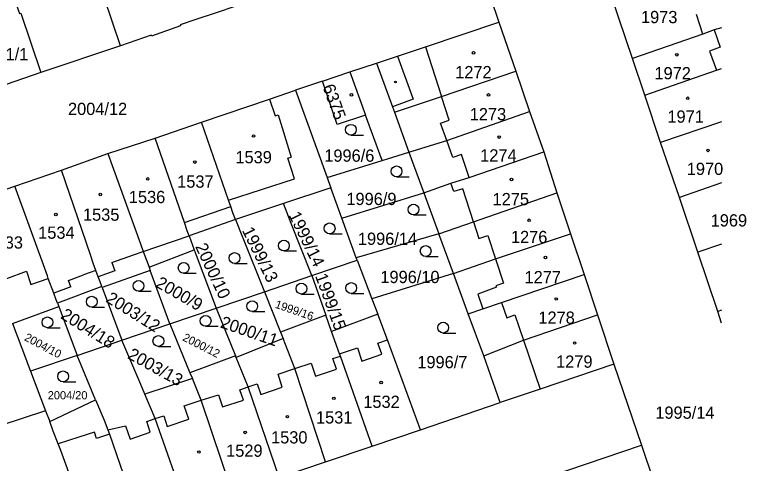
# Model space of a CAD drawing. Extents: x -564952 to -564307, y -1202373 to -1201847.
# Drawn here: x -564412.8 to -564311.2, y -1202149.3 to -1202086.9 of the extents above; entities that cross this region are included whole.
import ezdxf

# ---------------------------------------------------------------- set-up
doc = ezdxf.new("R2010")
doc.units = 0
for name, color, linetype in [('Hranice parcel', 7, 'Continuous'), ('Parcelní čísla', 7, 'Continuous'), ('Vnitřní kresba', 7, 'Continuous'), ('Značky budov', 7, 'Continuous'), ('Značky kultur', 7, 'Continuous')]:
    doc.layers.add(name, color=color, linetype=linetype)

msp = doc.modelspace()

# ---------------------------------------------------------------- linework, layer by layer
at = {"layer": 'Hranice parcel'}
for p, q in [((-564350.67, -1202072.89), (-564345.58, -1202087.99)), ((-564398.11, -1202091.24), (-564401.53, -1202081.18)), ((-564327.05, -1202093.01), (-564330.1, -1202083.96)), ((-564355.78, -1202091.38), (-564345.58, -1202087.99)), ((-564345.58, -1202087.99), (-564343.21, -1202094.78)), ((-564398.11, -1202091.24), (-564409.17, -1202094.97)), ((-564325.33, -1202098.13), (-564327.05, -1202093.01)), ((-564366.26, -1202094.88), (-564362.59, -1202093.65)), ((-564409.17, -1202094.97), (-564416.99, -1202097.64)), ((-564370.08, -1202096.16), (-564366.26, -1202094.88)), ((-564366.26, -1202094.88), (-564364.09, -1202100.88)), ((-564343.21, -1202094.78), (-564341.34, -1202100.38)), ((-564370.08, -1202096.16), (-564373.83, -1202097.42)), ((-564368.05, -1202102.21), (-564370.08, -1202096.16)), ((-564373.83, -1202097.42), (-564369.45, -1202109.57)), ((-564323.12, -1202104.71), (-564325.33, -1202098.13)), ((-564341.34, -1202100.38), (-564339.35, -1202105.98)), ((-564364.09, -1202100.88), (-564368.05, -1202102.21)), ((-564361.81, -1202107.21), (-564364.09, -1202100.88)), ((-564393.32, -1202104.11), (-564386.86, -1202101.86)), ((-564314.65, -1202101.83), (-564323.12, -1202104.71)), ((-564399.87, -1202106.23), (-564393.32, -1202104.11)), ((-564320.52, -1202112.35), (-564323.12, -1202104.71)), ((-564406.3, -1202108.52), (-564399.87, -1202106.23)), ((-564399.87, -1202106.23), (-564395.37, -1202118.77)), ((-564361.81, -1202107.21), (-564358.07, -1202106.05)), ((-564358.07, -1202106.05), (-564356.01, -1202111.68)), ((-564339.35, -1202105.98), (-564337.55, -1202111.69)), ((-564369.45, -1202109.57), (-564361.81, -1202107.21)), ((-564412.8, -1202110.76), (-564406.3, -1202108.52)), ((-564369.45, -1202109.57), (-564369.31, -1202109.97)), ((-564369.31, -1202109.97), (-564368.94, -1202110.98)), ((-564314.65, -1202110.31), (-564320.52, -1202112.35)), ((-564419.59, -1202113.07), (-564412.8, -1202110.76)), ((-564368.94, -1202110.98), (-564375.49, -1202113.18)), ((-564368.01, -1202113.53), (-564368.94, -1202110.98)), ((-564367.39, -1202115.22), (-564356.01, -1202111.68)), ((-564356.01, -1202111.68), (-564353.91, -1202117.36)), ((-564337.55, -1202111.69), (-564335.66, -1202117.4)), ((-564317.96, -1202119.94), (-564320.52, -1202112.35)), ((-564375.49, -1202113.18), (-564382.14, -1202115.41)), ((-564367.39, -1202115.22), (-564368.01, -1202113.53)), ((-564382.14, -1202115.41), (-564382.52, -1202114.47)), ((-564382.14, -1202115.41), (-564388.61, -1202117.64)), ((-564365.4, -1202120.7), (-564367.39, -1202115.22)), ((-564388.61, -1202117.64), (-564387.89, -1202119.58)), ((-564353.91, -1202117.36), (-564365.4, -1202120.7)), ((-564351.88, -1202122.89), (-564353.91, -1202117.36)), ((-564335.66, -1202117.4), (-564333.75, -1202123.03)), ((-564394.17, -1202122), (-564387.89, -1202119.58)), ((-564365.28, -1202121.04), (-564365.4, -1202120.7)), ((-564315.2, -1202128.18), (-564317.96, -1202119.94)), ((-564394.54, -1202121.02), (-564394.17, -1202122)), ((-564371.54, -1202123.17), (-564365.28, -1202121.04)), ((-564365.28, -1202121.04), (-564363.22, -1202126.43)), ((-564394.01, -1202122.45), (-564400.66, -1202124.84)), ((-564394.17, -1202122), (-564394.01, -1202122.45)), ((-564391.26, -1202129.88), (-564394.01, -1202122.45)), ((-564378.14, -1202125.42), (-564371.54, -1202123.17)), ((-564371.54, -1202123.17), (-564369.61, -1202128.66)), ((-564351.88, -1202122.89), (-564363.22, -1202126.43)), ((-564349.85, -1202128.48), (-564351.88, -1202122.89)), ((-564333.75, -1202123.03), (-564331.88, -1202128.64)), ((-564400.71, -1202124.7), (-564406.86, -1202127.03)), ((-564400.66, -1202124.84), (-564400.71, -1202124.7)), ((-564400.66, -1202124.84), (-564397.94, -1202132.15)), ((-564384.86, -1202127.7), (-564378.14, -1202125.42)), ((-564378.14, -1202125.42), (-564375.91, -1202131.05)), ((-564363.22, -1202126.43), (-564362.41, -1202128.56)), ((-564413.14, -1202129.85), (-564406.69, -1202127.47)), ((-564406.86, -1202127.03), (-564406.69, -1202127.47)), ((-564406.69, -1202127.47), (-564404.13, -1202134.26)), ((-564391.26, -1202129.88), (-564384.86, -1202127.7)), ((-564384.86, -1202127.7), (-564382.17, -1202134.31)), ((-564369.61, -1202128.66), (-564375.91, -1202131.05)), ((-564368.81, -1202130.94), (-564369.61, -1202128.66)), ((-564362.41, -1202128.56), (-564368.81, -1202130.94)), ((-564347.66, -1202134.31), (-564349.85, -1202128.48)), ((-564331.88, -1202128.64), (-564329.6, -1202135.47)), ((-564314.65, -1202129.79), (-564315.2, -1202128.18)), ((-564413.14, -1202129.85), (-564411.2, -1202134.99)), ((-564397.94, -1202132.15), (-564391.26, -1202129.88)), ((-564391.26, -1202129.88), (-564388.48, -1202136.67)), ((-564375.56, -1202131.94), (-564382.08, -1202134.54)), ((-564375.91, -1202131.05), (-564375.56, -1202131.94)), ((-564404.13, -1202134.26), (-564397.94, -1202132.15)), ((-564404.13, -1202134.26), (-564410.64, -1202136.47)), ((-564401.59, -1202140.42), (-564404.13, -1202134.26)), ((-564382.17, -1202134.31), (-564388.48, -1202136.67)), ((-564382.08, -1202134.54), (-564382.17, -1202134.31)), ((-564345.41, -1202140.82), (-564347.66, -1202134.31)), ((-564329.6, -1202135.47), (-564325.78, -1202146.73)), ((-564410.64, -1202136.47), (-564408.53, -1202141.96)), ((-564388.48, -1202136.67), (-564388.15, -1202137.47)), ((-564388.15, -1202137.47), (-564394.75, -1202139.64)), ((-564407.95, -1202143.46), (-564401.59, -1202140.42)), ((-564356.49, -1202144.6), (-564345.41, -1202140.82)), ((-564408.53, -1202141.96), (-564407.95, -1202143.46)), ((-564407.49, -1202144.77), (-564407.95, -1202143.46)), ((-564363.18, -1202146.87), (-564356.49, -1202144.6)), ((-564369.64, -1202149.05), (-564363.18, -1202146.87)), ((-564325.78, -1202146.73), (-564323.81, -1202152.55)), ((-564376.1, -1202151.25), (-564369.64, -1202149.05))]:
    msp.add_line(p, q, dxfattribs=at)
for points in [[(-564412.56, -1202085.59), (-564412.16, -1202086.79), (-564411.96, -1202086.73), (-564409.17, -1202094.97)], [(-564381.99, -1202085.72), (-564385, -1202086.73), (-564387.67, -1202087.58)], [(-564387.67, -1202087.58), (-564389.85, -1202088.36), (-564389.8, -1202088.5), (-564393.82, -1202089.94), (-564393.87, -1202089.8), (-564398.11, -1202091.24)], [(-564314.65, -1202088.74), (-564315.68, -1202089.06), (-564317.24, -1202089.63), (-564327.05, -1202093.01)], [(-564362.59, -1202093.65), (-564359.67, -1202092.68), (-564355.78, -1202091.38)], [(-564362.59, -1202093.65), (-564360.37, -1202099.72), (-564360.1, -1202100.47)], [(-564360.1, -1202100.47), (-564353.54, -1202098.29), (-564343.21, -1202094.78)], [(-564325.33, -1202098.13), (-564315.36, -1202094.65), (-564314.65, -1202094.4)], [(-564386.86, -1202101.86), (-564377.46, -1202098.66), (-564373.83, -1202097.42)], [(-564358.07, -1202106.05), (-564352.82, -1202104.42), (-564341.34, -1202100.38)], [(-564382.52, -1202114.47), (-564382.83, -1202113.57), (-564383.13, -1202112.69), (-564386.86, -1202101.86)], [(-564388.61, -1202117.64), (-564388.86, -1202116.97), (-564389.26, -1202115.82), (-564393.32, -1202104.11)], [(-564356.01, -1202111.68), (-564352.26, -1202110.34), (-564349.71, -1202109.53), (-564339.35, -1202105.98)], [(-564400.71, -1202124.7), (-564400.96, -1202124.03), (-564401.23, -1202123.33), (-564401.55, -1202122.45), (-564401.93, -1202121.45), (-564402.31, -1202120.31), (-564406.3, -1202108.52)], [(-564408.17, -1202123.57), (-564408.28, -1202123.22), (-564412.8, -1202110.76)], [(-564353.91, -1202117.36), (-564349.09, -1202115.72), (-564337.55, -1202111.69)], [(-564371.54, -1202123.17), (-564374.5, -1202115.7), (-564374.55, -1202115.55), (-564375.49, -1202113.18)], [(-564382.14, -1202115.41), (-564381.17, -1202117.83), (-564381.13, -1202117.93), (-564378.14, -1202125.42)], [(-564351.88, -1202122.89), (-564346.05, -1202120.84), (-564335.66, -1202117.4)], [(-564395.37, -1202118.77), (-564394.97, -1202119.84), (-564394.54, -1202121.02)], [(-564387.89, -1202119.58), (-564387.61, -1202120.33), (-564384.86, -1202127.7)], [(-564314.65, -1202118.82), (-564317.96, -1202119.94)], [(-564406.86, -1202127.03), (-564407.05, -1202126.54), (-564407.39, -1202125.62), (-564408.17, -1202123.57)], [(-564349.85, -1202128.48), (-564347.81, -1202127.79), (-564345.21, -1202126.91), (-564333.75, -1202123.03)], [(-564356.49, -1202144.6), (-564361.07, -1202132.1), (-564362.41, -1202128.56)], [(-564347.66, -1202134.31), (-564342.17, -1202132.13), (-564331.88, -1202128.64)], [(-564314.65, -1202128), (-564315.2, -1202128.18)], [(-564369.64, -1202149.05), (-564373.91, -1202136.11), (-564375.56, -1202131.94)], [(-564363.18, -1202146.87), (-564367.6, -1202134.39), (-564367.73, -1202134.04), (-564368.81, -1202130.94)], [(-564394.75, -1202139.64), (-564395.32, -1202138.3), (-564397.94, -1202132.15)], [(-564411.2, -1202134.99), (-564411.1, -1202135.26), (-564410.64, -1202136.47)], [(-564376.1, -1202151.25), (-564380.41, -1202138.65), (-564382.08, -1202134.54)], [(-564329.6, -1202135.47), (-564339.84, -1202138.95), (-564345.41, -1202140.82)], [(-564382.59, -1202153.39), (-564386.91, -1202140.5), (-564388.15, -1202137.47)], [(-564388.94, -1202155.54), (-564393.3, -1202143.04), (-564394.75, -1202139.64)], [(-564401.59, -1202140.42), (-564400.42, -1202143.26), (-564399.87, -1202144.59), (-564399.66, -1202145.21), (-564395.37, -1202157.69)], [(-564408.53, -1202141.96), (-564414.93, -1202144.06), (-564419.54, -1202145.57)], [(-564401.92, -1202159.96), (-564405.48, -1202150.04), (-564406.41, -1202147.46), (-564406.78, -1202146.53), (-564407.49, -1202144.77)], [(-564344.81, -1202153.14), (-564340.24, -1202151.6), (-564336.01, -1202150.19), (-564325.78, -1202146.73)]]:
    msp.add_lwpolyline(points, dxfattribs=at)
at = {"layer": 'Vnitřní kresba'}
for p, q in [((-564317.24, -1202089.63), (-564318.14, -1202086.92)), ((-564315.68, -1202089.06), (-564314.87, -1202091.46)), ((-564355.78, -1202091.38), (-564353.54, -1202098.29)), ((-564314.87, -1202091.46), (-564316.35, -1202092.01)), ((-564316.35, -1202092.01), (-564315.36, -1202094.65)), ((-564359.67, -1202092.68), (-564357.49, -1202098.67)), ((-564352.47, -1202101.6), (-564353.54, -1202098.29)), ((-564377.46, -1202098.66), (-564376.67, -1202101)), ((-564357.49, -1202098.67), (-564360.37, -1202099.72)), ((-564376.67, -1202101), (-564376.24, -1202100.85)), ((-564376.24, -1202100.85), (-564374.45, -1202106.71)), ((-564360.1, -1202100.47), (-564358.07, -1202106.05)), ((-564353.67, -1202102.02), (-564352.47, -1202101.6)), ((-564352.82, -1202104.42), (-564353.67, -1202102.02)), ((-564351.98, -1202106.78), (-564352.82, -1202104.42)), ((-564350.79, -1202106.36), (-564351.98, -1202106.78)), ((-564349.71, -1202109.53), (-564350.79, -1202106.36)), ((-564374.89, -1202106.85), (-564374.45, -1202106.71)), ((-564373.96, -1202109.73), (-564374.89, -1202106.85)), ((-564383.13, -1202112.69), (-564373.96, -1202109.73)), ((-564351.85, -1202111.52), (-564352.26, -1202110.34)), ((-564350.57, -1202111.12), (-564351.85, -1202111.52)), ((-564349.09, -1202115.72), (-564350.57, -1202111.12)), ((-564389.26, -1202115.82), (-564382.83, -1202113.57)), ((-564349.09, -1202115.72), (-564348.35, -1202118.01)), ((-564394.97, -1202119.84), (-564388.61, -1202117.64)), ((-564348.35, -1202118.01), (-564347.1, -1202117.61)), ((-564347.1, -1202117.61), (-564346.05, -1202120.84)), ((-564399.34, -1202121.35), (-564396.33, -1202120.31)), ((-564396.33, -1202120.31), (-564394.97, -1202119.84)), ((-564399.34, -1202121.35), (-564398.93, -1202122.54)), ((-564346.05, -1202120.84), (-564344.95, -1202124.24)), ((-564413.93, -1202123.58), (-564411.16, -1202122.55)), ((-564411.16, -1202122.55), (-564410.56, -1202124.41)), ((-564401.55, -1202122.45), (-564403.25, -1202123.09)), ((-564398.93, -1202122.54), (-564401.23, -1202123.33)), ((-564410.56, -1202124.41), (-564408.17, -1202123.57)), ((-564405.34, -1202123.88), (-564403.25, -1202123.09)), ((-564405.02, -1202124.72), (-564407.39, -1202125.62)), ((-564405.02, -1202124.72), (-564405.34, -1202123.88)), ((-564345.93, -1202124.8), (-564348.52, -1202125.76)), ((-564344.95, -1202124.24), (-564346, -1202124.6)), ((-564346, -1202124.6), (-564345.93, -1202124.8)), ((-564348.52, -1202125.76), (-564347.81, -1202127.79)), ((-564345.21, -1202126.91), (-564344.49, -1202129.04)), ((-564344.49, -1202129.04), (-564343.36, -1202128.65)), ((-564343.36, -1202128.65), (-564342.17, -1202132.13)), ((-564362.39, -1202132.59), (-564361.07, -1202132.1)), ((-564361.85, -1202134.08), (-564362.39, -1202132.59)), ((-564342.17, -1202132.13), (-564339.84, -1202138.95)), ((-564367.73, -1202134.04), (-564365.23, -1202133.22)), ((-564365.23, -1202133.22), (-564364.62, -1202135.06)), ((-564368.64, -1202134.71), (-564367.6, -1202134.39)), ((-564368.12, -1202136.17), (-564368.64, -1202134.71)), ((-564364.62, -1202135.06), (-564361.85, -1202134.08)), ((-564373.91, -1202136.11), (-564371.63, -1202135.35)), ((-564371.63, -1202135.35), (-564371.03, -1202137.14)), ((-564376.25, -1202136.88), (-564373.91, -1202136.11)), ((-564375.69, -1202138.66), (-564376.25, -1202136.88)), ((-564371.03, -1202137.14), (-564368.12, -1202136.17)), ((-564381.58, -1202139.06), (-564380.41, -1202138.65)), ((-564381.07, -1202140.49), (-564381.58, -1202139.06)), ((-564380.41, -1202138.65), (-564379.16, -1202138.21)), ((-564379.16, -1202138.21), (-564378.63, -1202139.72)), ((-564378.63, -1202139.72), (-564375.69, -1202138.66)), ((-564386.91, -1202140.5), (-564384.52, -1202139.73)), ((-564384.52, -1202139.73), (-564383.97, -1202141.42)), ((-564389.3, -1202141.28), (-564386.91, -1202140.5)), ((-564383.97, -1202141.42), (-564381.07, -1202140.49)), ((-564388.64, -1202143.12), (-564389.3, -1202141.28)), ((-564394.49, -1202143.43), (-564393.3, -1202143.04)), ((-564393.3, -1202143.04), (-564392.13, -1202142.66)), ((-564392.13, -1202142.66), (-564391.66, -1202144.15)), ((-564391.66, -1202144.15), (-564388.64, -1202143.12)), ((-564399.87, -1202144.59), (-564397.45, -1202144.07)), ((-564397.45, -1202144.07), (-564396.78, -1202145.92)), ((-564394, -1202144.93), (-564394.49, -1202143.43)), ((-564401.74, -1202144.94), (-564403.91, -1202145.62)), ((-564401.44, -1202145.82), (-564401.74, -1202144.94)), ((-564396.78, -1202145.92), (-564394, -1202144.93)), ((-564403.91, -1202145.62), (-564406.78, -1202146.53)), ((-564399.66, -1202145.21), (-564401.44, -1202145.82))]:
    msp.add_line(p, q, dxfattribs=at)
at = {"layer": 'Značky budov'}
for centre, radius in [((-564349.1, -1202092.23), 0.175), ((-564320.88, -1202092.5), 0.175), ((-564359.95, -1202096.28), 0.117), ((-564366.06, -1202098.06), 0.175), ((-564347.02, -1202098.08), 0.175), ((-564319.36, -1202098.54), 0.175), ((-564379.65, -1202103.78), 0.175), ((-564345.55, -1202103.94), 0.175), ((-564316.54, -1202105.79), 0.175), ((-564387.8, -1202107.41), 0.175), ((-564394.35, -1202109.75), 0.175), ((-564343.83, -1202109.83), 0.175), ((-564400.93, -1202111.91), 0.175), ((-564407.1, -1202114.7), 0.175), ((-564341.39, -1202115.49), 0.175), ((-564339.12, -1202120.67), 0.175), ((-564337.62, -1202126.44), 0.175), ((-564335.07, -1202132.55), 0.175), ((-564361.94, -1202138.03), 0.175), ((-564368.5, -1202140.23), 0.175), ((-564374.96, -1202142.78), 0.175), ((-564380.82, -1202144.97), 0.175), ((-564387.24, -1202147.69), 0.175)]:
    msp.add_circle(centre, radius, dxfattribs=at)
at = {"layer": 'Značky kultur'}
for p, q in [((-564366.14, -1202103.67), (-564364.39, -1202103.67)), ((-564359.79, -1202109.45), (-564358.04, -1202109.45)), ((-564357.44, -1202114.75), (-564355.69, -1202114.75)), ((-564369.09, -1202117.37), (-564367.34, -1202117.37)), ((-564375.44, -1202119.76), (-564373.69, -1202119.76)), ((-564355.75, -1202120.52), (-564354, -1202120.52)), ((-564382.29, -1202121.49), (-564380.54, -1202121.49)), ((-564389.36, -1202122.86), (-564387.61, -1202122.86)), ((-564395.63, -1202125.36), (-564393.88, -1202125.36)), ((-564373, -1202125.74), (-564371.25, -1202125.74)), ((-564366.09, -1202125.66), (-564364.34, -1202125.66)), ((-564402.12, -1202127.56), (-564400.37, -1202127.56)), ((-564379.84, -1202128.18), (-564378.09, -1202128.18)), ((-564408.27, -1202130.42), (-564406.52, -1202130.42)), ((-564386.31, -1202130.22), (-564384.56, -1202130.22)), ((-564353.32, -1202131.16), (-564351.57, -1202131.16)), ((-564392.87, -1202133.02), (-564391.12, -1202133.02)), ((-564406.1, -1202137.93), (-564404.35, -1202137.93))]:
    msp.add_line(p, q, dxfattribs=at)
for centre in [(-564366.14, -1202102.92), (-564359.79, -1202108.7), (-564357.44, -1202114), (-564369.09, -1202116.62), (-564375.44, -1202119.01), (-564355.75, -1202119.77), (-564382.29, -1202120.74), (-564389.36, -1202122.11), (-564395.63, -1202124.61), (-564373, -1202124.99), (-564366.09, -1202124.91), (-564402.12, -1202126.81), (-564379.84, -1202127.43), (-564386.31, -1202129.47), (-564408.27, -1202129.67), (-564353.32, -1202130.41), (-564392.87, -1202132.27), (-564406.1, -1202137.18)]:
    msp.add_circle(centre, 0.75, dxfattribs=at)

# ---------------------------------------------------------------- texts
at = {"layer": 'Parcelní čísla'}
for s, height, p in [('1973', 1.7, (-564325.85, -1202088.11)), ('1611/1', 1.7, (-564417.88, -1202093.27)), ('1272', 1.7, (-564351.65, -1202095.76)), ('1972', 1.7, (-564323.98, -1202095.91)), ('2004/12', 1.7, (-564405.42, -1202100.87)), ('1273', 1.7, (-564349.63, -1202101.6)), ('1971', 1.7, (-564322.18, -1202101.94)), ('1539', 1.7, (-564382.17, -1202107.58)), ('1996/6', 1.7, (-564369.83, -1202107.36)), ('1274', 1.7, (-564348.18, -1202107.33)), ('1970', 1.7, (-564319.49, -1202109.2)), ('1537', 1.7, (-564390.26, -1202110.97)), ('1536', 1.7, (-564396.97, -1202113.11)), ('1996/9', 1.7, (-564366.76, -1202113.38)), ('1275', 1.7, (-564346.46, -1202113.4)), ('1535', 1.7, (-564403.34, -1202115.56)), ('1969', 1.7, (-564316.17, -1202116.36)), ('1534', 1.7, (-564409.56, -1202118.06)), ('1533', 1.7, (-564416.73, -1202119.43)), ('1996/14', 1.7, (-564365.16, -1202118.91)), ('1276', 1.7, (-564343.91, -1202118.67)), ('1996/10', 1.7, (-564362.04, -1202124.22)), ('1277', 1.7, (-564342.02, -1202124.24)), ('1278', 1.7, (-564340.1, -1202129.87)), ('1996/7', 1.7, (-564356.91, -1202136.05)), ('1279', 1.7, (-564337.64, -1202135.98)), ('2004/20', 1.14, (-564408.23, -1202140.37)), ('1532', 1.7, (-564364.41, -1202141.56)), ('1531', 1.7, (-564370.98, -1202143.73)), ('1995/14', 1.7, (-564323.86, -1202143.07)), ('1530', 1.7, (-564377.22, -1202146.5)), ('1529', 1.7, (-564383.46, -1202148.35))]:
    msp.add_text(s, height=height, dxfattribs=at).set_placement(p)
for s, height, rotation, p in [('6375', 1.7, 290, (-564370.09, -1202096.94)), ('1999/14', 1.7, 296, (-564374.82, -1202114.77)), ('1999/13', 1.7, 296, (-564381.29, -1202116.91)), ('2000/10', 1.7, 295, (-564387.79, -1202119.14)), ('2000/9', 1.7, 330, (-564393.37, -1202124.67)), ('1999/15', 1.7, 290, (-564371.13, -1202123.22)), ('2003/12', 1.7, 328, (-564400.28, -1202126.76)), ('1999/16', 1.14, 341, (-564376.76, -1202127.63)), ('2004/18', 1.7, 328, (-564406.57, -1202129.04)), ('2000/11', 1.7, 341, (-564384.38, -1202130.36)), ('2004/10', 1.14, 332, (-564411.58, -1202132.12)), ('2000/12', 1.14, 333, (-564389.6, -1202132.14)), ('2003/13', 1.7, 331, (-564397.26, -1202134.62))]:
    msp.add_text(s, height=height, rotation=rotation, dxfattribs=at).set_placement(p)

doc.saveas('drawing.dxf')
